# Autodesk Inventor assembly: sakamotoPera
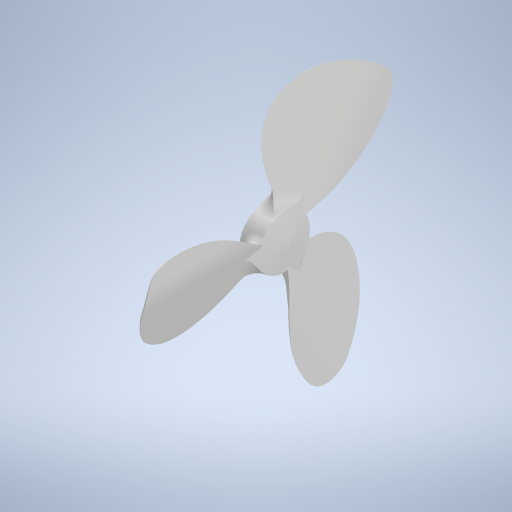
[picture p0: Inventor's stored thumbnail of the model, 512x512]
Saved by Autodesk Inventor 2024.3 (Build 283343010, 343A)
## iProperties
Created: 2025-10
Part Number: sakamotoPera
Document SubType Name: Assembly
Designer: kouki
Author: kouki
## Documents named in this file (3)
- F:\openFOAM\bathrobo\BRSMsakamoto\sakamotoPera.iam
- F:\openFOAM\bathrobo\BRSMsakamoto\9mm_new orimage pera.ipt
- F:\openFOAM\bathrobo\BRSMsakamoto\shaft.ipt
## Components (2 placed, 2 different names)
1. 9mm_new orimage pera:1 — 挿入:1
2. shaft:1 — メイト:1, 挿入:1
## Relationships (2: Mate 1, Insert 1)
- メイト:1 [Mate]: shaft:1
- 挿入:1 [Insert]: 9mm_new orimage pera:1 ↔ shaft:1
